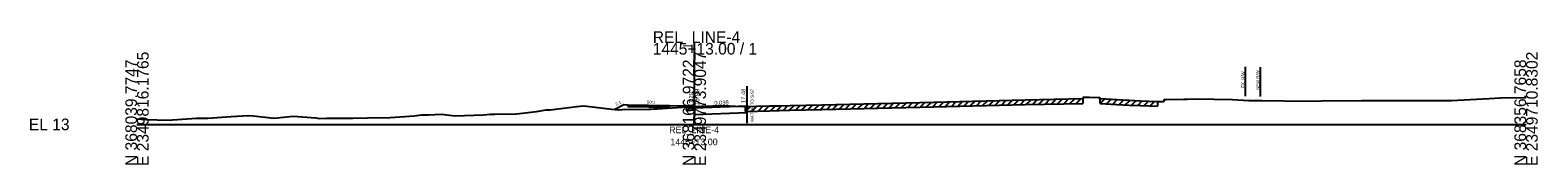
# Model space of a CAD drawing. Extents: x -26 to 2350146, y -10 to 368200.
# Drawn here: x 1974.3 to 2336.9, y 5990.3 to 6022.4 of the extents above; entities that cross this region are included whole.
import ezdxf

# ---------------------------------------------------------------- set-up
doc = ezdxf.new("R2010")
doc.units = 0
for name, color, linetype in [('RD_GPK_XS_Cell', 7, 'Continuous'), ('RD_XS_Base', 7, 'Continuous'), ('RD_XS_CurbBase', 7, 'Continuous'), ('RD_XS_CurbFront', 7, 'Continuous'), ('RD_XS_CurbTop', 7, 'Continuous'), ('RD_XS_EarthShd', 7, 'Continuous'), ('RD_XS_ExGround', 7, 'Continuous'), ('RD_XS_ExPaveRet', 7, 'Continuous'), ('RD_XS_ExRW', 7, 'Continuous'), ('RD_XS_NewRW', 7, 'Continuous'), ('RD_XS_Pave', 7, 'Continuous'), ('RD_XS_SW', 7, 'Continuous'), ('RD_XS_SWbase', 7, 'Continuous'), ('RD_XS_TieSlope', 7, 'Continuous'), ('RD_XS_TX_Elev_EX', 7, 'Continuous'), ('RD_XS_TX_Elev_PR', 7, 'Continuous'), ('RD_XS_TX_MatchLine', 7, 'Continuous'), ('RD_XS_TX_Slope', 7, 'Continuous'), ('RD_XS_TX_Station', 7, 'Continuous'), ('RD_XS_TX_TOC', 7, 'Continuous')]:
    doc.layers.add(name, color=color, linetype=linetype)

msp = doc.modelspace()

# ---------------------------------------------------------------- linework, layer by layer
at = {"layer": 'RD_GPK_XS_Cell'}
for p, q in [((2134.04, 6000), (2134.04, 6019.59)), ((2000, 6000), (2134.04, 6000)), ((2134.04, 6000), (2334.04, 6000))]:
    msp.add_line(p, q, dxfattribs=at)
at = {"layer": 'RD_XS_Base'}
msp.add_line((2134.04, 6002.35), (2146.68, 6002.84), dxfattribs=at)
at = {"layer": 'RD_XS_CurbBase'}
for p, q in [((2132.04, 6004.38), (2132.04, 6003.38)), ((2132.04, 6003.38), (2132.54, 6003.38)), ((2132.54, 6003.38), (2134.04, 6003.47)), ((2134.04, 6002.35), (2134.04, 6003.47))]:
    msp.add_line(p, q, dxfattribs=at)
at = {"layer": 'RD_XS_CurbFront'}
msp.add_line((2134.04, 6003.47), (2134.04, 6003.97), dxfattribs=at)
at = {"layer": 'RD_XS_CurbTop'}
for p, q in [((2132.54, 6004.38), (2132.04, 6004.38)), ((2132.62, 6003.88), (2132.54, 6004.38)), ((2134.04, 6003.97), (2132.62, 6003.88)), ((2134.04, 6003.99), (2134.04, 6003.97))]:
    msp.add_line(p, q, dxfattribs=at)
at = {"layer": 'RD_XS_EarthShd'}
for p, q in [((2118.04, 6004.66), (2117.04, 6004.68)), ((2132.04, 6004.38), (2128.04, 6004.46))]:
    msp.add_line(p, q, dxfattribs=at)
at = {"layer": 'RD_XS_ExGround'}
msp.add_lwpolyline([(2000, 6001.32), (2002.24, 6001.17), (2007.43, 6001.01), (2014.35, 6001.49), (2017.03, 6001.5), (2022.64, 6001.92), (2026.76, 6002.12), (2028.05, 6002.09), (2032.88, 6001.49), (2037.55, 6001.98), (2043, 6001.59), (2043.84, 6001.45), (2045.59, 6001.48), (2051.88, 6001.5), (2055.41, 6001.6), (2060.87, 6001.65), (2066.77, 6002.09), (2068.34, 6002.28), (2070.11, 6002.33), (2073.26, 6002.5), (2076.41, 6002.04), (2083.36, 6002.29), (2084.98, 6002.5), (2086.07, 6002.5), (2091.24, 6002.52), (2096.05, 6003.08), (2098.39, 6003.5), (2099.4, 6003.5), (2105.74, 6004.32), (2107.23, 6004.49), (2108.19, 6004.37), (2114.22, 6003.7), (2115.83, 6003.51), (2116.78, 6003.56), (2123.08, 6003.65), (2123.57, 6003.68), (2124.37, 6003.71), (2125.09, 6003.75), (2133.62, 6004.28), (2134.04, 6004.29), (2135.77, 6004.36), (2141.1, 6004.55), (2142.43, 6004.48), (2145.67, 6004.27), (2152.08, 6004.43), (2154.1, 6004.48), (2154.42, 6004.46), (2157.05, 6004.55), (2164.68, 6004.74), (2191.66, 6005.38), (2213.6, 6005.91), (2227.44, 6006.21), (2227.61, 6006.51), (2227.96, 6006.51), (2229.07, 6006.53), (2231.14, 6006.49), (2231.5, 6006.49), (2231.66, 6006.19), (2235.67, 6005.95), (2238.62, 6005.79), (2241.3, 6005.66), (2245.4, 6005.54), (2246.23, 6005.5), (2246.91, 6005.47), (2247.07, 6005.97), (2247.57, 6005.97), (2251.71, 6006.06), (2252.55, 6006.07), (2254.44, 6006.11), (2263.47, 6006.02), (2267.38, 6005.75), (2270.61, 6005.72), (2275.8, 6005.65), (2281.4, 6005.58), (2284.88, 6005.68), (2294.58, 6005.72), (2302.87, 6005.74), (2309.92, 6005.72), (2316.1, 6005.73), (2325.17, 6006.26), (2327.93, 6006.42), (2334.04, 6006.44)], dxfattribs=at)
at = {"layer": 'RD_XS_ExPaveRet'}
for p, q in [((2146.36, 6003.14), (2147.53, 6004.31)), ((2146.36, 6003.14), (2146.36, 6004.28)), ((2147.86, 6003.18), (2149.03, 6004.35)), ((2149.36, 6003.22), (2150.53, 6004.39)), ((2150.86, 6003.25), (2152.03, 6004.43)), ((2152.36, 6003.29), (2153.53, 6004.47)), ((2153.86, 6003.33), (2155, 6004.48)), ((2155.36, 6003.35), (2156.54, 6004.53)), ((2156.86, 6003.4), (2158.03, 6004.57)), ((2158.36, 6003.44), (2159.53, 6004.61)), ((2159.86, 6003.47), (2161.03, 6004.65)), ((2161.36, 6003.51), (2162.53, 6004.68)), ((2162.86, 6003.55), (2164.03, 6004.72)), ((2164.36, 6003.59), (2165.53, 6004.76)), ((2164.68, 6003.59), (2191.66, 6004.23)), ((2165.86, 6003.62), (2167.03, 6004.79)), ((2167.36, 6003.66), (2168.53, 6004.83)), ((2168.86, 6003.69), (2170.03, 6004.86)), ((2170.36, 6003.73), (2171.53, 6004.9)), ((2171.86, 6003.76), (2173.03, 6004.93)), ((2173.36, 6003.8), (2174.53, 6004.97)), ((2174.86, 6003.84), (2176.03, 6005.01)), ((2176.36, 6003.87), (2177.53, 6005.04)), ((2177.86, 6003.91), (2179.03, 6005.08)), ((2179.36, 6003.94), (2180.53, 6005.11)), ((2180.86, 6003.98), (2182.03, 6005.15)), ((2182.36, 6004.01), (2183.53, 6005.18)), ((2183.86, 6004.05), (2185.03, 6005.22)), ((2185.36, 6004.08), (2186.53, 6005.25)), ((2186.86, 6004.12), (2188.03, 6005.29)), ((2188.36, 6004.15), (2189.53, 6005.33)), ((2189.86, 6004.19), (2191.03, 6005.36)), ((2191.36, 6004.23), (2192.53, 6005.4)), ((2191.66, 6004.23), (2213.6, 6004.77)), ((2192.86, 6004.26), (2194.03, 6005.43)), ((2194.36, 6004.3), (2195.53, 6005.47)), ((2195.86, 6004.34), (2197.03, 6005.51)), ((2197.36, 6004.37), (2198.53, 6005.54)), ((2198.86, 6004.41), (2200.03, 6005.58)), ((2200.36, 6004.45), (2201.53, 6005.62)), ((2201.86, 6004.48), (2203.03, 6005.65)), ((2203.36, 6004.52), (2204.53, 6005.69)), ((2204.86, 6004.55), (2206.03, 6005.73)), ((2206.36, 6004.59), (2207.53, 6005.76)), ((2207.86, 6004.63), (2209.03, 6005.8)), ((2209.36, 6004.66), (2210.53, 6005.84)), ((2210.86, 6004.7), (2212.03, 6005.87)), ((2212.36, 6004.74), (2213.53, 6005.91)), ((2213.6, 6004.77), (2227.44, 6005.06)), ((2213.86, 6004.77), (2215.02, 6005.94)), ((2215.36, 6004.81), (2216.52, 6005.97)), ((2216.86, 6004.84), (2218.02, 6006.01)), ((2218.36, 6004.87), (2219.52, 6006.04)), ((2219.86, 6004.9), (2221.02, 6006.07)), ((2221.36, 6004.93), (2222.52, 6006.1)), ((2222.86, 6004.97), (2224.02, 6006.13)), ((2224.36, 6005), (2225.52, 6006.17)), ((2225.86, 6005.03), (2227.02, 6006.2)), ((2227.44, 6006.21), (2227.44, 6005.06)), ((2231.66, 6005.05), (2231.66, 6006.19)), ((2231.66, 6005.05), (2232.74, 6006.13)), ((2231.66, 6005.05), (2235.67, 6004.81)), ((2233.16, 6004.96), (2234.24, 6006.04)), ((2234.66, 6004.87), (2235.74, 6005.95)), ((2235.67, 6004.81), (2238.62, 6004.64)), ((2236.16, 6004.78), (2237.24, 6005.86)), ((2237.66, 6004.7), (2238.74, 6005.78)), ((2238.62, 6004.64), (2241.3, 6004.52)), ((2239.16, 6004.62), (2240.25, 6005.71)), ((2240.66, 6004.55), (2241.76, 6005.65)), ((2241.3, 6004.52), (2245.4, 6004.4)), ((2242.16, 6004.49), (2243.27, 6005.61)), ((2243.66, 6004.45), (2244.77, 6005.56)), ((2245.4, 6005.54), (2245.4, 6004.4)), ((2146.36, 6003.14), (2152.08, 6003.28)), ((2152.08, 6003.28), (2154.1, 6003.34)), ((2154.1, 6003.34), (2154.42, 6003.32)), ((2154.42, 6003.32), (2157.05, 6003.4)), ((2157.05, 6003.4), (2164.68, 6003.59))]:
    msp.add_line(p, q, dxfattribs=at)
at = {"layer": 'RD_XS_ExRW'}
msp.add_line((2266.61, 6006.81), (2266.61, 6013.81), dxfattribs=at)
at = {"layer": 'RD_XS_NewRW'}
msp.add_line((2270.16, 6006.73), (2270.16, 6013.73), dxfattribs=at)
at = {"layer": 'RD_XS_Pave'}
for p, q in [((2146.68, 6009.21), (2146.68, 6000.28)), ((2134.04, 6003.99), (2146.68, 6004.48))]:
    msp.add_line(p, q, dxfattribs=at)
at = {"layer": 'RD_XS_SW'}
msp.add_line((2128.04, 6004.46), (2118.04, 6004.66), dxfattribs=at)
at = {"layer": 'RD_XS_SWbase'}
for p, q in [((2118.04, 6004.66), (2118.04, 6004.33)), ((2118.04, 6004.33), (2128.04, 6004.13)), ((2128.04, 6004.13), (2128.04, 6004.46))]:
    msp.add_line(p, q, dxfattribs=at)
at = {"layer": 'RD_XS_TieSlope'}
msp.add_line((2117.04, 6004.68), (2114.91, 6003.62), dxfattribs=at)

# ---------------------------------------------------------------- texts
at = {"layer": 'RD_GPK_XS_Cell'}
for s, p in [('REL_LINE-4', (2124.04, 6019.59)), ('1445+13.00 / 1', (2124.04, 6016.79)), ('EL 13', (1974, 5998.6))]:
    msp.add_text(s, height=2.8, dxfattribs=at).set_placement(p)
for s, p in [('N 368039.7747', (2000, 5990)), ('E 2349816.1765', (2002.8, 5990)), ('N 368166.9722', (2134.04, 5990)), ('E 2349773.9047', (2136.84, 5990)), ('N 368356.7658', (2334.04, 5990)), ('E 2349710.8302', (2336.84, 5990))]:
    msp.add_text(s, height=2.8, rotation=90, dxfattribs=at).set_placement(p)
at = {"layer": 'RD_XS_ExRW'}
msp.add_text('EX. R/W ', height=0.75, rotation=90, dxfattribs=at).set_placement((2266.36, 6008.76))
at = {"layer": 'RD_XS_NewRW'}
msp.add_text('NEW R/W ', height=0.75, rotation=90, dxfattribs=at).set_placement((2269.91, 6008.31))
at = {"layer": 'RD_XS_TX_Elev_EX'}
msp.add_text('17.29', height=1, rotation=90, dxfattribs=at).set_placement((2133.76, 6004.29))
at = {"layer": 'RD_XS_TX_Elev_PR'}
for s, height, rotation, p in [(' 16.99', 1.2, 90, (2135.24, 6003.99)), ('17.48', 1, 90, (2146.31, 6005.14)), ('0.039', 1, 2.2105, (2138.85, 6004.64))]:
    msp.add_text(s, height=height, rotation=rotation, dxfattribs=at).set_placement(p)
at = {"layer": 'RD_XS_TX_MatchLine'}
msp.add_text('MATCH TO S-97', height=0.75, rotation=90, dxfattribs=at).set_placement((2148.3, 6000.64))
at = {"layer": 'RD_XS_TX_Slope'}
for s, rotation, p in [('2:1', 26.5651, (2115.26, 6004.45)), ('50:1', 358.8542, (2122.62, 6004.98))]:
    msp.add_text(s, height=0.75, rotation=rotation, dxfattribs=at).set_placement(p)
at = {"layer": 'RD_XS_TX_Station'}
for s, p in [('REL_LINE-4', (2127.97, 5997.89)), ('1445+13.00', (2128.27, 5994.99))]:
    msp.add_text(s, height=1.6, dxfattribs=at).set_placement(p)
at = {"layer": 'RD_XS_TX_TOC'}
msp.add_text('TOCLT', height=0.05, dxfattribs=at).set_placement((2132.59, 6004.33))

doc.saveas('drawing.dxf')
